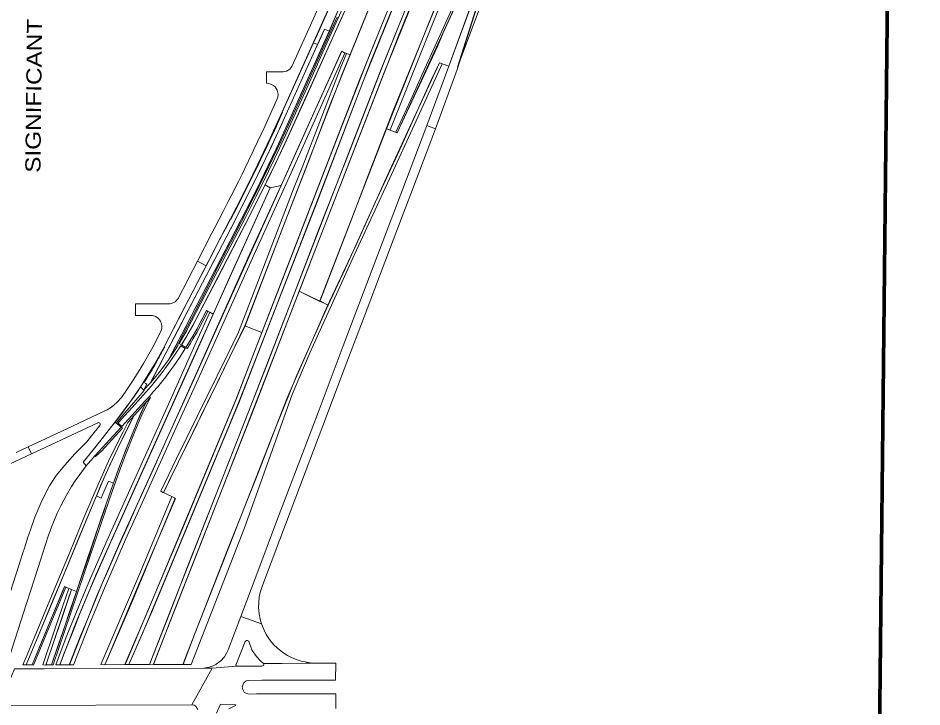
# Model space of a CAD drawing. Extents: x 2356576 to 2377878, y 6966390 to 6990634.
# Drawn here: x 2364785 to 2367164, y 6980469 to 6982282 of the extents above; entities that cross this region are included whole.
import ezdxf

# ---------------------------------------------------------------- set-up
doc = ezdxf.new("R2010")
doc.units = 0
doc.header["$LTSCALE"] = 7.1
for name, color, linetype, lineweight in [('10', 7, 'Continuous', 13), ('11', 7, 'Continuous', 13), ('14', 7, 'Continuous', 13), ('19', 7, 'Continuous', 13), ('27', 7, 'Continuous', 13), ('8', 7, 'Continuous', 13), ('9', 7, 'Continuous', 13)]:
    doc.layers.add(name, color=color, linetype=linetype, lineweight=lineweight)
doc.layers.add('5', color=7, linetype='Continuous')

msp = doc.modelspace()

# ---------------------------------------------------------------- linework, layer by layer
at = {"layer": '10'}
for points in [[(2365755.194, 6981991.376), (2365902.214, 6982360.642), (2366046.74, 6982718.556), (2366138, 6982979.704), (2366175.283, 6983097.481), (2366229.458, 6983287.408), (2366238.716, 6983284.023), (2366179.369, 6983078.746), (2366116.743, 6982891.307), (2366048.311, 6982698.115), (2365994.134, 6982555.118), (2365944.295, 6982437.526), (2365869.956, 6982251.846), (2365764.301, 6981987.966)], [(2365779.464, 6981981.99), (2365818.731, 6982067.726), (2365847.232, 6982130.64), (2365936.737, 6982327.156), (2365984.751, 6982439.606), (2366036.01, 6982566.981), (2366089.297, 6982704.822), (2366135.082, 6982829.484), (2366178.158, 6982951.643), (2366231.45, 6983112.504), (2366261.82, 6983214.885), (2366278.079, 6983273.764), (2366281.817, 6983272.511), (2366248.494, 6983156.518), (2366188.384, 6982969.176), (2366128.047, 6982800.485), (2366070.965, 6982645.218), (2366010.659, 6982493.71), (2365972.153, 6982398.727), (2365923.433, 6982286.819), (2365880.109, 6982192.439), (2365783.175, 6981980.555)], [(2365382.326, 6981472.187), (2365638.459, 6982134.483), (2365690.965, 6982264.676), (2365919.769, 6982830.212), (2365961.124, 6982815.17), (2365878.037, 6982598.874), (2365683.228, 6982117.169), (2365427.095, 6981454.873)], [(2365882.313, 6982829.01), (2365847.731, 6982749.843), (2365710.644, 6982446.425), (2365635.978, 6982280.409), (2365544.853, 6982078.348), (2365487.048, 6981951.296), (2365443.092, 6981859.537), (2365435.264, 6981843.443), (2365448.587, 6981835.455), (2365478.016, 6981842.032), (2365523.478, 6981943.673), (2365568.337, 6982042.774), (2365636.764, 6982194.747), (2365659.01, 6982185.741), (2365919.769, 6982830.212)], [(2365525.252, 6981563.427), (2365748.722, 6982139.518), (2365926.701, 6982579.174), (2365983.351, 6982557.356), (2365770.13, 6982032.607), (2365704.868, 6981863.544), (2365668.159, 6981766.769), (2365579.762, 6981536.853)], [(2365637.061, 6982195.149), (2365568.854, 6982044.615), (2365495.194, 6981880.389), (2365389.946, 6981650.652), (2365269.237, 6981379.061), (2365158.001, 6981133.989), (2365051.72, 6980897.746), (2364992.991, 6980761.643), (2364950.368, 6980655.339), (2364920.824, 6980580.213), (2364931.452, 6980580.208), (2364971.956, 6980682.892), (2365012.456, 6980782.154), (2365068.403, 6980909.918), (2365112.212, 6981006.966), (2365188.623, 6981175.499), (2365258.957, 6981332.436), (2365389.114, 6981621.572), (2365520.262, 6981911.849), (2365592.275, 6982072.161), (2365645.407, 6982190.49)], [(2365649.811, 6982188.921), (2365659.325, 6982185.594), (2365603.18, 6982045.877), (2365548.38, 6981902.152), (2365482.343, 6981731.578), (2365382.676, 6981472.733), (2365342.479, 6981391.018), (2365292.2, 6981288.521), (2365222.979, 6981145.77), (2365188.49, 6981075.51), (2365168.175, 6981033.01), (2365161.146, 6981037.16), (2365202.702, 6981123.54), (2365256.678, 6981233.859), (2365335.463, 6981393.968), (2365365.383, 6981455.963), (2365435.964, 6981638.467), (2365511.947, 6981837.043), (2365532.742, 6981889.127), (2365633.232, 6982148.83)], [(2365219.446, 6980581.231), (2365249.243, 6980659.666), (2365343.913, 6980898.599), (2365494.192, 6981284.706), (2365598.849, 6981523.321), (2365674.734, 6981685.536), (2365757.53, 6981868.585), (2365810.725, 6981984.959), (2365894.281, 6982164.605), (2365901.339, 6982161.768), (2365832.542, 6982012.246), (2365773.669, 6981881.765), (2365671.027, 6981659.863), (2365553.548, 6981402.764), (2365506.721, 6981292.025), (2365381.325, 6980940.513), (2365240.546, 6980581.225)], [(2365448.587, 6981835.455), (2365339.521, 6981593.573), (2365263.82, 6981424.587), (2365156.383, 6981186.7), (2365089.688, 6981037.793), (2365058.153, 6980968.181), (2365029.41, 6980904.326), (2364998.436, 6980834.19), (2364972.483, 6980773.737), (2364947.366, 6980712.238), (2364929.227, 6980667.226), (2364905.376, 6980606.809), (2364895.005, 6980580.063), (2364920.173, 6980579.958), (2364950.834, 6980658.131), (2364969.692, 6980704.125), (2364991.18, 6980755.68), (2365007.087, 6980794.412), (2365024.947, 6980835.761), (2365050.508, 6980894.318), (2365074.764, 6980947.916), (2365096.385, 6980995.66), (2365141.873, 6981096.153), (2365177.871, 6981176.756), (2365239.822, 6981313.888), (2365325.973, 6981505.201), (2365478.016, 6981842.032)], [(2365141.795, 6980580.864), (2365187.636, 6980699.526), (2365407.521, 6981258.707), (2365525.252, 6981563.427), (2365601.21, 6981526.526), (2365596.204, 6981515.258), (2365518.917, 6981342.862), (2365463.851, 6981205.43), (2365418.07, 6981087.407), (2365334.315, 6980878.291), (2365219.019, 6980581.169)], [(2365290.106, 6981508.007), (2365299.063, 6981503.534), (2365243.897, 6981381.018), (2365189.078, 6981260.497), (2365086.939, 6981033.354), (2364992.016, 6980820.646), (2364938.552, 6980692.18), (2364894.91, 6980580.111), (2364884.434, 6980580.113), (2364912.034, 6980652.59), (2364953.596, 6980753.955), (2364977.16, 6980810.174), (2365016.075, 6980900.329), (2365051.195, 6980978.263), (2365116.59, 6981122.408), (2365185.444, 6981275.574), (2365254.296, 6981429.582)], [(2365227.1, 6981415.081), (2365235.733, 6981429.143), (2365247.965, 6981450.04), (2365249.67, 6981453.049), (2365256.268, 6981464.942), (2365259.378, 6981470.688), (2365281.336, 6981512.691), (2365284.744, 6981510.492), (2365259.788, 6981463.043), (2365255.525, 6981455.313), (2365246.162, 6981438.894), (2365237.887, 6981424.971), (2365230.547, 6981413.048)], [(2365013.95, 6980580.518), (2365083.539, 6980742.181), (2365198.806, 6981019.036), (2365168.298, 6981033.544), (2365284.22, 6981271.054), (2365315.187, 6981334.709), (2365382.326, 6981472.187), (2365427.095, 6981454.873), (2365358.55, 6981277.634), (2365127.849, 6980723.726), (2365066.472, 6980580.62)], [(2365123.047, 6981271.984), (2365133.549, 6981283.469), (2365116.843, 6981251.176), (2365105.726, 6981225.495), (2365090.905, 6981190.132), (2365067.169, 6981130.356), (2365052.1, 6981090.504), (2365032.648, 6981035.951), (2365014.653, 6980982.88), (2364976.003, 6980869.251), (2364907.867, 6980668.038), (2364877.903, 6980579.988), (2364873.753, 6980579.967), (2364892.074, 6980634.419), (2364921.587, 6980719.841), (2364962.165, 6980841.688), (2365003.368, 6980963.223), (2365023.535, 6981021.661), (2365039.192, 6981066.645), (2365049.989, 6981096.335), (2365060.079, 6981123.195), (2365068.628, 6981145.261), (2365081.08, 6981176.627), (2365092.333, 6981204.035), (2365098.234, 6981218.345), (2365107.861, 6981240.568), (2365114.593, 6981255.624)], [(2365074.499, 6981218.334), (2365090.74, 6981236.467), (2365062.918, 6981181.422), (2365046.65, 6981148.606), (2365016.613, 6981082.747), (2364977.73, 6980991.344), (2364943.71, 6980909.607), (2364908.343, 6980823.835), (2364872.781, 6980739.2), (2364838.135, 6980655.338), (2364812.923, 6980595.054), (2364806.725, 6980580.002), (2364798.091, 6980579.867), (2364809.198, 6980606.335), (2364843.696, 6980689.288), (2364888.172, 6980796.538), (2364922.209, 6980878.725), (2364960.495, 6980971.063), (2364995.727, 6981054.465), (2365027.155, 6981123.799), (2365061.6, 6981193.566)], [(2365004.504, 6981142.347), (2364988.78, 6981128.857), (2364987.673, 6981129.869), (2365056.981, 6981205.434), (2365059.879, 6981202.904)], [(2365003.527, 6980580.62), (2365109.885, 6980831.446), (2365190.251, 6981023.491), (2365199.471, 6981018.092), (2365106.749, 6980800.7), (2365013.948, 6980580.417)], [(2364911.465, 6980784.629), (2364890.222, 6980733.974), (2364876.372, 6980700.426), (2364826.321, 6980579.706), (2364822.172, 6980580.115), (2364844.223, 6980633.043), (2364883.283, 6980726.668), (2364907.849, 6980785.939)], [(2364918.616, 6980781.237), (2364926.106, 6980778.815), (2364904.301, 6980714.115), (2364858.871, 6980579.485), (2364850.574, 6980580.036), (2364883.147, 6980677.085), (2364903.301, 6980735.054)]]:
    msp.add_lwpolyline(points, close=True, dxfattribs=at)
for points in [[(2365819.992, 6982430.326), (2365712.279, 6982163.697), (2365569.031, 6981791.562), (2365409.775, 6981383.657), (2365369.291, 6981278.492), (2365343.816, 6981216.213), (2365247.137, 6980984.665), (2365177.483, 6980818.074), (2365111.499, 6980660.62), (2365076.945, 6980580.901), (2365066.893, 6980580.691), (2365090.068, 6980634.527), (2365121.736, 6980710.264), (2365214.285, 6980930.368), (2365314.183, 6981171.218), (2365360.146, 6981281.161), (2365403.534, 6981393.405), (2365485.138, 6981605.546), (2365612.772, 6981934.596), (2365709.934, 6982184.59), (2365853.802, 6982539.175)], [(2365870.105, 6982441.934), (2365787.702, 6982237.601), (2365632.494, 6981841.05), (2365578.567, 6981701.782), (2365550.058, 6981628.195), (2365474.358, 6981431.988), (2365383.848, 6981199.777), (2365272.904, 6980917.449), (2365164.246, 6980641.057), (2365141.718, 6980581.543), (2365131.01, 6980581.215), (2365184.321, 6980717.35), (2365230.519, 6980836.423), (2365318.455, 6981058.395), (2365374.263, 6981201.362), (2365440.451, 6981371.942), (2365514.741, 6981563.803), (2365579.814, 6981732.808), (2365653.759, 6981922.488), (2365742.815, 6982151.461), (2365838.502, 6982388.877)], [(2365643.758, 6982317.4), (2365601.381, 6982224.013), (2365544.823, 6982098.133), (2365489.105, 6981974.342), (2365460.705, 6981914.001), (2365427.381, 6981845.108), (2365416.696, 6981823.504), (2365411.721, 6981813.523), (2365383.58, 6981757.96), (2365354.743, 6981702.234), (2365255.225, 6981510.263), (2365246.148, 6981492.753), (2365236.856, 6981474.83), (2365229.44, 6981460.524), (2365219.348, 6981442.498), (2365209.26, 6981425.603), (2365215.041, 6981422.202), (2365221.358, 6981432.461), (2365225.817, 6981439.871), (2365229.393, 6981445.897), (2365232.915, 6981451.937), (2365244.82, 6981473.38), (2365254.553, 6981491.644), (2365274.041, 6981529.43), (2365374.297, 6981722.573), (2365384.633, 6981742.528), (2365415.85, 6981804.697), (2365439.269, 6981851.677), (2365464.532, 6981903.62), (2365492.942, 6981963.874), (2365526.142, 6982037.026), (2365591.927, 6982182.882), (2365650.347, 6982312.549)], [(2365624.808, 6982285.106), (2365570.107, 6982162.704), (2365516.046, 6982043.452), (2365477.731, 6981958.973), (2365445.65, 6981891.406), (2365392.632, 6981784.654), (2365352.929, 6981707.93), (2365316.615, 6981636.964), (2365241.704, 6981491.25), (2365220.604, 6981452.667), (2365207.017, 6981424.006), (2365206.281, 6981424.593), (2365205.671, 6981423.539), (2365206.384, 6981424.571), (2365206.995, 6981423.903), (2365205.409, 6981421.015), (2365200.748, 6981412.145), (2365183.152, 6981385.87), (2365255.534, 6981526.809), (2365342.754, 6981694.842), (2365412.698, 6981830.531), (2365474.015, 6981958.577), (2365559.108, 6982147.752), (2365604.053, 6982247.785), (2365625.372, 6982297.094)]]:
    msp.add_lwpolyline(points, dxfattribs=at)
at = {"layer": '11'}
for points in [[(2365591.582, 6982253.559), (2365604.418, 6982247.969), (2365615.433, 6982273.831), (2365624.049, 6982294.566), (2365639.626, 6982333.269), (2365648.82, 6982356.908), (2365658.293, 6982381.936), (2365665.1, 6982400.283), (2365681.562, 6982443.393), (2365689.362, 6982463.13), (2365695.982, 6982479.633), (2365682.893, 6982484.611), (2365677.531, 6982472.708), (2365672.28, 6982461.052), (2365663.88, 6982442.405), (2365654.095, 6982420.686), (2365645.671, 6982401.986), (2365633.408, 6982374.765), (2365622.057, 6982349.567), (2365603.68, 6982308.773), (2365591.413, 6982281.543), (2365577.246, 6982250.095), (2365562.571, 6982217.52), (2365573.511, 6982212.589)], [(2365601.21, 6981526.526), (2365645.897, 6981622.787), (2365679.3, 6981695.749), (2365725.081, 6981796.79), (2365789.629, 6981936.584), (2365871.457, 6982117.663), (2365894.112, 6982164.858), (2365918.836, 6982155.854), (2366007.685, 6982399.844), (2365979.568, 6982416.671), (2365964.313, 6982380.948), (2365928.167, 6982297.092), (2365903.725, 6982243.407), (2365911.213, 6982260.563), (2365889.126, 6982207.528), (2365834.645, 6982091.146), (2365783.175, 6981980.555), (2365755.194, 6981991.376), (2365579.24, 6981537.817)], [(2365604.418, 6982247.969), (2365589.051, 6982213.018), (2365558.598, 6982145.399), (2365519.72, 6982059.095), (2365494.484, 6982003.185), (2365465.926, 6981941.432), (2365441.67, 6981890.446), (2365403.66, 6981813.054), (2365357.369, 6981722.508), (2365323.65, 6981656.422), (2365302.648, 6981616.403), (2365268.42, 6981550.764), (2365222.183, 6981462.096), (2365193.831, 6981407.473), (2365181.678, 6981383.599), (2365171.586, 6981369.803), (2365156.23, 6981349.578), (2365134.648, 6981323.301), (2365174.545, 6981400.259), (2365195.964, 6981441.58), (2365214.257, 6981476.867), (2365223.715, 6981495.112), (2365298.467, 6981639.305), (2365346.608, 6981732.169), (2365404.215, 6981845.61), (2365452.675, 6981946.13), (2365527.097, 6982109.557), (2365562.282, 6982187.662), (2365583.588, 6982235.219), (2365591.582, 6982253.559)], [(2365227.1, 6981415.081), (2365232.443, 6981423.783), (2365237.849, 6981432.757), (2365245.228, 6981445.363), (2365249.956, 6981453.565), (2365255.337, 6981463.265), (2365261.87, 6981475.456), (2365266.238, 6981483.811), (2365281.153, 6981512.478), (2365299.063, 6981503.534), (2365448.587, 6981835.455), (2365435.264, 6981843.443), (2365381.303, 6981735.75), (2365306.235, 6981591.03), (2365268.724, 6981518.921), (2365249.48, 6981481.879), (2365236.453, 6981458.118), (2365233.347, 6981452.681), (2365230.276, 6981447.385), (2365223.449, 6981435.882), (2365217.566, 6981426.256), (2365215.041, 6981422.202)], [(2365048.882, 6981216.823), (2365093.688, 6981266.688), (2365136.929, 6981314.864), (2365164.676, 6981349.42), (2365183.368, 6981374.89), (2365200.949, 6981400.42), (2365213.545, 6981419.701), (2365225.505, 6981412.541), (2365212.635, 6981392.692), (2365199.419, 6981373.365), (2365195.082, 6981367.204), (2365182.485, 6981349.865), (2365173.79, 6981338.392), (2365162.747, 6981324.324), (2365152.744, 6981312.005), (2365141.235, 6981298.393), (2365130.925, 6981286.582), (2365121.142, 6981275.976), (2365110.422, 6981264.411), (2365075.873, 6981226.443), (2365058.868, 6981207.458), (2365048.559, 6981216.412)], [(2365107.814, 6981311.509), (2365116.91, 6981302.424), (2365100.437, 6981283.193), (2365084.065, 6981263.844), (2365066.614, 6981243.226), (2365052.569, 6981226.624), (2365043.939, 6981216.431), (2365040.52, 6981219.312), (2365050.144, 6981231.578), (2365060.918, 6981245.477), (2365078.711, 6981269.411), (2365091.097, 6981286.856), (2365100.21, 6981300.137)], [(2365123.047, 6981271.984), (2365090.947, 6981236.822), (2365076.05, 6981208.127), (2365059.542, 6981174.146), (2365046.873, 6981148.698), (2365025.937, 6981103.767), (2365002.657, 6981051.099), (2364991.988, 6981025.236), (2365004.469, 6981019.006), (2365008.867, 6981029.666), (2365023.392, 6981064.008), (2365036.28, 6981058.508), (2365046.107, 6981085.778), (2365054.74, 6981109.083), (2365069.941, 6981148.682), (2365080.877, 6981176.132), (2365097.625, 6981216.939), (2365109.8, 6981245.044), (2365115.108, 6981256.76)], [(2364956.545, 6981113.907), (2364990.566, 6981155.647), (2365006.667, 6981176.168), (2365031.179, 6981207.408), (2365040.52, 6981219.312), (2365056.981, 6981205.434), (2364987.673, 6981129.869), (2364978.165, 6981119.12), (2364969.258, 6981109.248), (2364964.897, 6981103.542)], [(2364991.988, 6981025.236), (2364960.38, 6980949.907), (2364917.099, 6980845.321), (2364878.448, 6980751.871), (2364849.057, 6980681.455), (2364833.154, 6980643.132), (2364806.783, 6980579.889), (2364822.082, 6980579.889), (2364846.843, 6980639.733), (2364863.954, 6980680.51), (2364887.044, 6980736.331), (2364905.827, 6980781.318), (2364907.779, 6980786.263), (2364926.249, 6980778.591), (2364939.146, 6980772.848), (2364970.399, 6980863.959), (2364993.499, 6980934.045), (2365011.843, 6980986.291), (2365018.353, 6981006.394), (2365030.493, 6981041.952), (2365036.28, 6981058.508), (2365023.392, 6981064.008), (2365008.867, 6981029.666), (2365004.469, 6981019.006)], [(2364939.146, 6980772.848), (2364921.933, 6980722.311), (2364906.456, 6980676.395), (2364889.793, 6980627.617), (2364874.461, 6980582.444), (2364873.702, 6980579.968), (2364858.681, 6980579.973), (2364861.207, 6980586.955), (2364877.722, 6980636.138), (2364902.302, 6980707.562), (2364915.457, 6980746.846), (2364926.249, 6980778.591)]]:
    msp.add_lwpolyline(points, close=True, dxfattribs=at)
at = {"layer": '14'}
msp.add_lwpolyline([(2365076.877, 6980580.654), (2365137.08, 6980719.881), (2365367.781, 6981273.789), (2365461.852, 6981516.617), (2365574.007, 6981802.884), (2365692.555, 6982113.562), (2365887.306, 6982595.122), (2365971.367, 6982815.286), (2366004.778, 6982908.478), (2366038.112, 6983004.166), (2366082.132, 6983145.315), (2366130.019, 6983312.415), (2366161.868, 6983304.047), (2366143.319, 6983241.14), (2366110.114, 6983127.305), (2366081.433, 6983034.548), (2366055.631, 6982958.608), (2366021.586, 6982853.798), (2365979.937, 6982741.059), (2365917.432, 6982582.926), (2365739.453, 6982143.27), (2365397.89, 6981261.541), (2365178.33, 6980703.186), (2365131.062, 6980580.83)], close=True, dxfattribs=at)
at = {"layer": '19', "lineweight": 40}
msp.add_lwpolyline([(2363758.773, 6990629.355), (2367158.576, 6990592.767), (2366922.891, 6968646.236), (2363523.088, 6968682.826)], close=True, dxfattribs=at)
at = {"layer": '27'}
msp.add_line((2365562.57, 6982217.518), (2365563.938, 6982216.902), dxfattribs=at)
for points in [[(2365491.028, 6982029.491), (2365573.511, 6982212.589), (2365562.57, 6982217.518), (2365480.087, 6982034.421)], [(2365120.052, 6981321.176), (2365124.502, 6981318.878), (2365116.62, 6981303.682), (2365133.154, 6981321.567), (2365354.45, 6981747.299)], [(2365343.797, 6981752.824), (2365232.324, 6981537.792), (2365169.806, 6981417.192)]]:
    msp.add_lwpolyline(points, dxfattribs=at)
for centre, radius, start, end in [((2360293.489, 6984370.897), 5690.078, 332.59784, 335.74923), ((2360293.489, 6984370.895), 5700.578, 332.59784, 335.74923), ((2364129.386, 6981956.557), 1173.416, 330.77867, 332.21764), ((2364129.386, 6981956.557), 1173.416, 332.21764, 332.59727), ((2364129.386, 6981956.557), 1173.416, 329.55897, 330.77867), ((2364129.386, 6981956.557), 1173.416, 328.33864, 329.55897), ((2364129.386, 6981956.557), 1173.416, 327.32522, 328.33864)]:
    msp.add_arc(centre, radius, start, end, dxfattribs=at)
at = {"layer": '8', "lineweight": 40}
for points in [[(2363753.827, 6990634.409), (2367163.63, 6990597.713), (2366927.837, 6968641.182), (2363518.034, 6968677.88)], [(2363758.773, 6990629.355), (2367158.576, 6990592.767), (2366922.891, 6968646.236), (2363523.088, 6968682.826)]]:
    msp.add_lwpolyline(points, close=True, dxfattribs=at)
at = {"layer": '9'}
for points in [[(2366386.09, 6983481.738), (2366346.323, 6983323.551), (2366311.213, 6983199.294), (2366257.388, 6983025.444), (2366239.847, 6982972.323), (2366196.527, 6982847.592), (2366124.393, 6982651.358), (2366014.116, 6982347.761), (2365941.689, 6982153.706), (2365984.869, 6982289.006), (2366008.121, 6982366.225), (2366042.841, 6982461.664), (2366132.371, 6982706.493), (2366169.589, 6982809.533), (2366240.869, 6983012.04), (2366278.99, 6983132.27), (2366328.211, 6983303.549), (2366380.158, 6983505.924)], [(2366387.461, 6983487.86), (2366356.587, 6983360.535), (2366322.61, 6983239.34), (2366288.02, 6983121.358), (2366247.271, 6982993.261), (2366197.044, 6982848.419), (2366146.817, 6982710.967), (2366058.931, 6982469.584), (2366017.942, 6982392.49), (2365969.647, 6982238.89), (2365940.579, 6982146.744), (2365883.552, 6981990.735), (2365861.27, 6981999.705), (2365918.836, 6982155.854), (2366007.956, 6982399.836), (2365979.568, 6982416.671), (2366036.45, 6982557.144), (2366086.518, 6982686.053), (2366129.09, 6982801.848), (2366205.907, 6983020.002), (2366231.916, 6983102.649), (2366259.212, 6983192.485), (2366299.856, 6983335.931), (2366315.093, 6983394.652)], [(2365642.827, 6982395.672), (2365586.835, 6982271.381), (2365563.151, 6982218.807), (2365548.058, 6982185.503), (2365489.131, 6982054.663), (2365448.956, 6981966.646), (2365415.456, 6981895.947), (2365388.728, 6981841.501), (2365330.794, 6981727.786), (2365319.2, 6981705.416), (2365289.944, 6981648.973), (2365280.116, 6981630.012), (2365257.285, 6981642.434), (2365295.494, 6981716.14), (2365303.335, 6981731.265), (2365325.079, 6981773.226), (2365338.514, 6981799.415), (2365346.082, 6981814.318), (2365365.182, 6981852.42), (2365374.716, 6981871.711), (2365382.183, 6981886.95), (2365400.976, 6981926.547), (2365405.952, 6981936.247), (2365434.68, 6981997.516), (2365467.479, 6982069.736), (2365468.883, 6982074.333), (2365469.586, 6982082.271), (2365467.362, 6982092.336), (2365461.84, 6982101.078), (2365457.177, 6982105.249), (2365447.642, 6982109.833), (2365439.467, 6982110.926), (2365439.318, 6982140.892), (2365482.948, 6982141.219), (2365491.886, 6982143.142), (2365500.186, 6982148.37), (2365505.939, 6982155.112), (2365619.997, 6982408.301)], [(2364756.875, 6980582.707), (2364806.743, 6980738.694), (2364829.604, 6980809.487), (2364844.451, 6980855.67), (2364850.772, 6980875.108), (2364857.976, 6980897.166), (2364865.767, 6980921.43), (2364874.88, 6980947.072), (2364888.111, 6980978.918), (2364898.549, 6981000.838), (2364912.514, 6981026.755), (2364926.185, 6981049.502), (2364936.035, 6981064.391), (2364947.844, 6981081.392), (2364957.351, 6981093.983), (2364964.897, 6981103.542), (2364956.545, 6981113.907), (2364993.509, 6981159.398), (2365037.97, 6981216.062), (2365060.551, 6981244.997), (2365083.124, 6981275.551), (2365110.616, 6981315.796), (2365143.561, 6981369.491), (2365167.024, 6981411.799), (2365214.894, 6981504.179), (2365233.998, 6981541.027), (2365280.116, 6981630.012), (2365257.285, 6981642.434), (2365206.358, 6981544.195), (2365198.531, 6981535.811), (2365189.459, 6981531.643), (2365184.405, 6981530.437), (2365094.152, 6981529.949), (2365094.778, 6981499.616), (2365139.56, 6981499.872), (2365147.727, 6981496.8), (2365155.112, 6981491.502), (2365160.245, 6981484.827), (2365163.216, 6981477.415), (2365164.057, 6981472.181), (2365163.824, 6981465.768), (2365161.416, 6981457.503), (2365140.102, 6981416.579), (2365115.571, 6981372.98), (2365090.196, 6981332.084), (2365072.333, 6981305.425), (2365057.333, 6981284.22), (2365045.893, 6981271.236), (2365038.329, 6981264.321), (2365031.289, 6981258.372), (2365019.866, 6981251.257), (2365012.297, 6981247.435), (2364929.033, 6981208.553), (2364858.93, 6981176.172), (2364812.002, 6981153.838), (2364820.882, 6981135.875), (2364871.638, 6981159.541), (2364995.066, 6981217.297), (2364996.71, 6981217.879), (2364998.93, 6981217.301), (2365000.717, 6981215.976), (2365001.15, 6981214.872), (2365001.397, 6981213.716), (2365001.397, 6981211.981), (2365000.513, 6981210.443), (2364978.704, 6981182.719), (2364966.777, 6981167.446), (2364934.921, 6981135.126), (2364908.836, 6981105.98), (2364885.61, 6981078.783), (2364868.491, 6981051.273), (2364847.843, 6981011.636), (2364829.381, 6980968.581), (2364818.693, 6980938.056), (2364810.49, 6980913.434), (2364802.994, 6980889.997), (2364797.261, 6980872.351), (2364790.94, 6980852.775), (2364787.558, 6980841.608), (2364764.846, 6980770.954)], [(2364780.248, 6981138.971), (2364812.002, 6981153.838), (2364820.882, 6981135.875), (2364471.57, 6980972.489)], [(2365258.106, 6980462.941), (2365253.951, 6980469.592), (2365253.573, 6980470.348), (2365251.685, 6980471.859), (2365248.457, 6980473.888), (2365242.551, 6980475.198), (2365295.907, 6980571.365), (2365359.436, 6980577.049), (2365413.087, 6980577.049), (2365426.533, 6980576.836), (2365428.396, 6980577.28), (2365431.737, 6980579.636), (2365431.529, 6980583.694), (2365479.487, 6980583.958), (2365542.574, 6980584.168), (2365560.676, 6980584.734), (2365621.61, 6980584.453), (2365620.804, 6980540.003), (2365531.346, 6980540.08), (2365430.437, 6980539.661), (2365427.192, 6980539.603), (2365392.303, 6980539.117), (2365385.929, 6980537.655), (2365379.688, 6980533.005), (2365376.415, 6980526.562), (2365375.438, 6980521.977), (2365376.415, 6980514.846), (2365380.484, 6980508.425), (2365386.195, 6980504.439), (2365393.484, 6980503.184), (2365412.445, 6980503.581), (2365621.317, 6980503.708), (2365621.848, 6980464.911)], [(2365340.069, 6980464.453), (2365354.044, 6980471.255), (2365357.821, 6980473.522), (2365357.066, 6980475.412), (2365317.784, 6980476.546), (2365307.586, 6980453.116)]]:
    msp.add_lwpolyline(points, dxfattribs=at)
for points in [[(2365425.871, 6980688.075), (2365422.592, 6980699.968), (2365419.621, 6980713.977), (2365418.246, 6980731.016), (2365418.594, 6980744.175), (2365420.035, 6980759.059), (2365422.337, 6980770.608), (2365428.134, 6980789.287), (2365473.812, 6980910.407), (2365528.245, 6981054.008), (2365587.046, 6981208.944), (2365643.816, 6981358.049), (2365695.908, 6981496.117), (2365765.696, 6981679.616), (2365839.786, 6981875.391), (2365883.552, 6981990.735), (2365861.27, 6981999.705), (2365814.567, 6981876.738), (2365720.031, 6981627.299), (2365641.106, 6981419.515), (2365574.726, 6981244.348), (2365504.249, 6981058.53), (2365465.763, 6980957.461), (2365413.713, 6980818.955), (2365371.108, 6980707.189)], [(2365295.907, 6980571.365), (2365360.19, 6980577.044), (2365358.373, 6980579.017), (2365383.34, 6980641.729), (2365386.468, 6980644.027), (2365389.471, 6980644.586), (2365392.474, 6980642.358), (2365394.211, 6980637.4), (2365401.751, 6980617.988), (2365412.556, 6980602.401), (2365424.242, 6980590.177), (2365431.529, 6980583.694), (2365542.574, 6980584.168), (2365558.252, 6980584.725), (2365540.732, 6980587.682), (2365530.186, 6980589.813), (2365517.01, 6980594.028), (2365504.825, 6980599.148), (2365493.935, 6980604.842), (2365481.938, 6980612.677), (2365467.887, 6980624.091), (2365457.687, 6980633.807), (2365449.456, 6980643.623), (2365445.03, 6980649.823), (2365438.581, 6980659.81), (2365432.591, 6980671.55), (2365425.871, 6980688.075), (2365371.108, 6980707.189), (2365338.182, 6980619.691), (2365334.077, 6980610.445), (2365328.542, 6980601.641), (2365317.661, 6980589.535), (2365311.251, 6980585.141), (2365305.473, 6980581.178), (2365298.862, 6980577.934), (2365288.026, 6980573.744), (2365274.044, 6980571.409), (2365295.907, 6980571.365)], [(2364736.106, 6980473.474), (2364775.895, 6980569.652), (2364776.217, 6980569.457), (2364854.398, 6980569.554), (2365295.907, 6980571.365), (2365242.551, 6980475.198)]]:
    msp.add_lwpolyline(points, close=True, dxfattribs=at)

# ---------------------------------------------------------------- texts
at = {"layer": '5', "width": 1.2}
msp.add_text('SIGNIFICANT CHANGE', height=39.87, rotation=89.364, dxfattribs=at).set_placement((2364844.203, 6981875.121))

doc.saveas('drawing.dxf')
